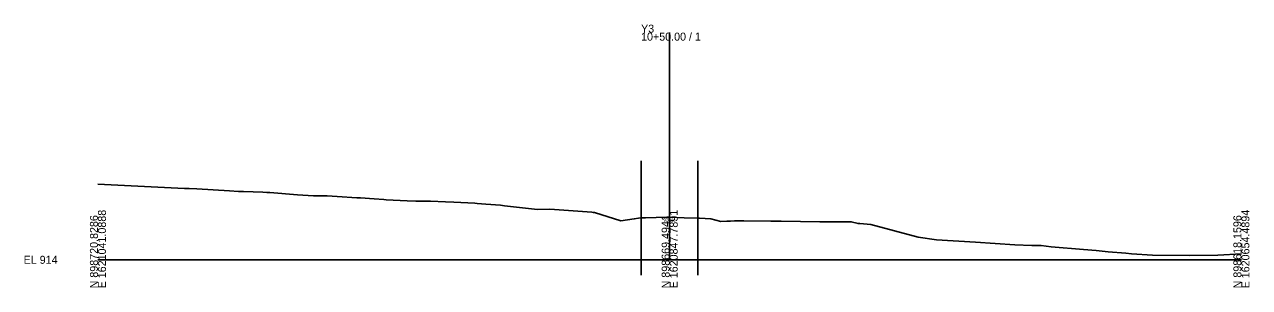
# Model space of a CAD drawing. Extents: x -26 to 3018, y -10 to 5545.
# Drawn here: x -25.7 to 402.8, y 490.3 to 582.3 of the extents above; entities that cross this region are included whole.
import ezdxf

# ---------------------------------------------------------------- set-up
doc = ezdxf.new("R2010")
doc.units = 0
for name, color, linetype in [('Exist Cross Section Cell', 7, 'Continuous'), ('Exist XS Center Line Elevation Label', 7, 'Continuous'), ('Exist XS Ground Line', 7, 'Continuous'), ('Scratch_Level_4', 7, 'Continuous')]:
    doc.layers.add(name, color=color, linetype=linetype)

msp = doc.modelspace()

# ---------------------------------------------------------------- linework, layer by layer
at = {"layer": 'Exist Cross Section Cell'}
for p, q in [((200, 500), (200, 579.44)), ((0, 500), (200, 500)), ((200, 500), (400, 500))]:
    msp.add_line(p, q, dxfattribs=at)
at = {"layer": 'Exist XS Ground Line'}
msp.add_lwpolyline([(0, 526.48), (30.25, 524.93), (30.81, 524.94), (31.86, 524.89), (34.58, 524.78), (46.02, 524.13), (49.13, 523.93), (50.93, 523.88), (57.72, 523.61), (59.11, 523.57), (59.47, 523.53), (60.11, 523.48), (69.82, 522.76), (75.46, 522.36), (80.17, 522.33), (83.63, 522.18), (90.51, 521.65), (91.81, 521.62), (96.68, 521.27), (99.98, 521.1), (100.86, 521.02), (108.16, 520.59), (111.21, 520.48), (116.34, 520.5), (121.56, 520.32), (124.51, 520.12), (131.9, 519.76), (132.69, 519.71), (135.65, 519.48), (140.86, 519.08), (142.25, 518.92), (153.71, 517.63), (158.06, 517.69), (172.81, 516.61), (173.29, 516.58), (173.66, 516.49), (182.86, 513.67), (187.62, 514.27), (189.04, 514.55), (190.03, 514.64), (191.49, 514.67), (199.06, 514.89), (200, 514.86), (205.02, 514.7), (209.9, 514.56), (210.49, 514.53), (214.36, 514.27), (216.18, 513.82), (217.85, 513.4), (219.99, 513.47), (221.31, 513.55), (222.72, 513.62), (223.3, 513.65), (225.94, 513.62), (235.37, 513.52), (238.97, 513.5), (245.72, 513.4), (252.53, 513.31), (256.07, 513.27), (263.5, 513.3), (265.93, 512.68), (266.49, 512.68), (270.33, 512.36), (286.92, 507.96), (293.29, 507.03), (307, 506.17), (320.77, 505.25), (326.68, 505.03), (329.96, 504.97), (333.45, 504.52), (344.78, 503.59), (349.19, 503.22), (353.44, 502.83), (359.54, 502.3), (361.61, 502.13), (368.91, 501.56), (381.81, 501.5), (391.82, 501.61), (400, 502.11)], dxfattribs=at)
at = {"layer": 'Scratch_Level_4'}
for p, q in [((190.03, 534.64), (190.03, 494.64)), ((209.89, 534.57), (209.89, 494.57))]:
    msp.add_line(p, q, dxfattribs=at)

# ---------------------------------------------------------------- texts
at = {"layer": 'Exist Cross Section Cell'}
for s, p in [('Y3', (190, 579.44)), ('10+50.00 / 1', (190, 576.64)), ('EL 914', (-26, 498.6))]:
    msp.add_text(s, height=2.8, dxfattribs=at).set_placement(p)
for s, p in [('N 898720.8286', (0, 490)), ('E 1621041.0888', (2.8, 490)), ('N 898669.4941', (200, 490)), ('E 1620847.7891', (202.8, 490)), ('N 898618.1596', (400, 490)), ('E 1620654.4894', (402.8, 490))]:
    msp.add_text(s, height=2.8, rotation=90, dxfattribs=at).set_placement(p)
at = {"layer": 'Exist XS Center Line Elevation Label'}
msp.add_text('928.86', height=1, dxfattribs=at).set_placement((197.86, 513.36))

doc.saveas('drawing.dxf')
